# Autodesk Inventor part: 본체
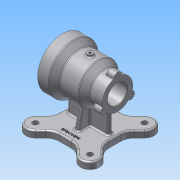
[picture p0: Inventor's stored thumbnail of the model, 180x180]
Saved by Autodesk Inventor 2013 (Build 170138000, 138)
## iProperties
Created: 2017-03
Part Number: 본체
Material: 알루미늄 6061
Document SubType Name: Modeling
Designer: Administrator
Density: 2.71 g/cm^3
Mass: 1008.17 g
Surface Area: 842.601 cm^2
Volume: 372.018 cm^3
Author: Administrator
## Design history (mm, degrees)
sketch "스케치1"
  geometry: L1 (50, 0)-(-50, 0); L2 (-50, 0)-(-50, 45); L3 (50, 27.5)-(27, 27.5); L4 (-30, 45)-(-19, 36); L5 (15, 36)-(27, 27.5); L6 (50, 27.5)-(50, 0); L7 (15, 36)-(-19, 36); L8 (-50, 45)-(-30, 45); L9 (-50, 0)-(-27, 0); L10 (-27, 0)-(-27, 35); L11 (-27, 35)-(-50, 35); L12 (-50, 35)-(-50, 0); L13 (-27, 0)-(20, 0); L14 (20, 0)-(20, 26); L15 (20, 26)-(-27, 26); L16 (-27, 26)-(-27, 0); L17 (20, 0)-(50, 0); L18 (50, 0)-(50, 17.5); L19 (50, 17.5)-(20, 17.5); L20 (20, 17.5)-(20, 0); 2 further points
  constraints: 40 end point, 10 parallel, 4 horizontal, 4 perpendicular, 1 coincident, 1 midpoint, 1 point on line
  dimensions: "d0" = 100 distance of L1.start L1.end; "d8" = 55 diameter of L3 L1; "d9" = 72 diameter of L7 L1; "d10" = 90 diameter of L8 L1; "d12" = 70 diameter of L11 L1; "d13" = 52 diameter of L15 L1; "d14" = 35 diameter of L19 L17; "d15" = 23 distance between parallel lines of L16 L2; "d16" = 47 distance between parallel lines of L14 L10; "d119" = 20 distance of L2.end L4.start; "d120" = 31 horizontal distance of L4.end L2.end; "d121" = 65 horizontal distance of L5.start L2.end; "d122" = 23 distance from line of L6 L3.end
revolve "회전2" sketch "스케치1" stored, may be unused: angle "d17" = 90 deg
chamfer "모따기1" distance "d18" = 1; stored, may be unused: second distance "d19" = 2, angle "d20" = 45 deg
fillet "모깎기1" dims "d21" = 3
node "작업 평면1"
sketch "스케치3"
  geometry: L1 (20.958, -45)-(-20.958, -45); L2 (-45, -20.958)-(-45, 20.958); L3 (-20.958, 45)-(20.958, 45); L4 (0, 0)-(82.902, 0); L5 (49.497, -49.497)-(66.497, -49.497); L6 (49.497, -49.497)-(66.497, -49.497); L7 (61.518, -37.477)-(45, -20.958); L8 (37.477, -61.518)-(20.958, -45); L9 (45, 20.958)-(45, -20.958); L10 (37.477, 61.518)-(20.958, 45); L11 (61.518, 37.477)-(45, 20.958); L12 (-61.518, 37.477)-(-45, 20.958); L13 (-37.477, 61.518)-(-20.958, 45); L14 (-37.477, -61.518)-(-20.958, -45); L15 (-61.518, -37.477)-(-45, -20.958); A1 r 17 centre (49.497, -49.497) between (37.477, -61.518) and (61.518, -37.477); A2 r 17 centre (49.497, 49.497) between (61.518, 37.477) and (37.477, 61.518); A3 r 17 centre (-49.497, 49.497) between (-37.477, 61.518) and (-61.518, 37.477); A4 r 17 centre (-49.497, -49.497) between (-61.518, -37.477) and (-37.477, -61.518); 2 further points
  constraints: 30 end point, 8 point on circle, 4 centre point, 4 horizontal, 3 parallel, 2 tangent, 1 coincident, 1 perpendicular, 33 other
  dimensions: "d25" = 45 distance from line of point (0, 0) L1; "d29" = 34 diameter of A1; "d34" = 360 deg dimension on point (0, 0) L5.start (derived)
extrude "돌출1" join sketch "스케치3" distance "d36" = 12; taper "d37" = 0 deg
fillet "모깎기2" dims "d38" = 25
hole "구멍1" diameter "d41" = 10; stored, may be unused: countersink angle "d45" = 90 deg, drill point angle "d47" = 118 deg; dims "d39" = 10, "d40" = 10, "d42" = 6, "d43" = 4, "d44" = 2, "d46" = 8
sketch "스케치4"
  geometry: L1 (-37, 4)-(37, 4); L2 (37, 4)-(37, -4); L3 (37, -4)-(-37, -4); L4 (-37, -4)-(-37, 4); L5 (-4, 25)-(4, 25); L6 (4, 25)-(4, -25); L7 (4, -25)-(-4, -25); L8 (-4, -25)-(-4, 25); 1 further point
  constraints: 16 end point, 4 parallel, 2 horizontal, 2 perpendicular
  dimensions: "d51" = 4 distance from line of point (0, 0) L1; "d52" = 8 distance of L3.end L1.start; "d53" = 4 distance from line of point (0, 0) L6; "d54" = 8 distance between parallel lines of L6 L8; "d55" = 74 distance of L1.start L1.end; "d56" = 37 distance from line of point (0, 0) L2; "d58" = 25 distance from line of L5 point (0, 0); "d124" = 25 distance from line of L7 point (0, 0)
extrude "돌출2" join sketch "스케치4" stored distance "d59" = 12; taper "d60" = 0 deg
extrude "돌출3" join sketch "스케치4" stored distance "d61" = 12; taper "d62" = 0 deg
feature "면 기울기1" dims angle "d63" = 10 deg
feature "면 기울기2" dims angle "d64" = 10 deg
fillet "모깎기3" dims "d65" = 3
node "작업 평면2"
sketch "스케치5"
  geometry: C1 r 5 at (0, 0); 1 further point
  constraints: 1 centre point, 1 coincident
  dimensions: "d67" = 10 diameter of C1
extrude "돌출4" join sketch "스케치5" stored distance "d68" = 12; taper "d69" = 0 deg
fillet "모깎기4" dims "d70" = 3
hole "구멍2" diameter "d73" = 4.1; stored, may be unused: countersink angle "d77" = 90 deg, drill point angle "d79" = 118 deg; dims "d71" = 10, "d72" = 10, "d74" = 6, "d75" = 4, "d76" = 2, "d78" = 30
sketch "스케치6"
  geometry: A1 r 27.5 centre (0, 0) between (0, 27.5) and (-6.943, 26.609) reference; A2 r 7 centre (0, 27.5) between (6.943, 26.609) and (-6.943, 26.609)
  constraints: 5 point on circle, 1 centre point
  dimensions: "d80" = 14 diameter of A2
extrude "돌출5" join sketch "스케치6" distance "d81" = 15; taper "d82" = 0 deg
fillet "모깎기5" dims "d83" = 3
fillet "모깎기6" dims "d84" = 1
hole "구멍3" diameter "d87" = 3.2; stored, may be unused: countersink angle "d91" = 90 deg, drill point angle "d93" = 118 deg; dims "d88" = 9, "d89" = 4, "d90" = 2, "d92" = 11, "d94" = 10, "d95" = 10
fillet "모깎기7" dims "d99" = 3
sketch "스케치7"
  geometry: 1 further point
hole "구멍4" sketch "스케치7" at (0, 40) diameter "d101" = 3.2; stored, may be unused: countersink angle "d105" = 90 deg, drill point angle "d107" = 118 deg; dims "d102" = 9, "d103" = 4, "d104" = 2, "d106" = 11
node "작업 평면3"
sketch "스케치9"
  geometry: L1 (45, -10.603)-(45, 10.603) reference; 3 further points
  constraints: 1 coincident, 1 other
  dimensions: "d114" = 35 distance of point (0, 0) point (0, -35); "d115" = 45 distance from line of L1 point (0, -35)
feature "엠보싱1" sketch "스케치9" dims "d0" = 100, "d8" = 55, "d9" = 72, "d10" = 90, "d12" = 70, "d13" = 52, "d14" = 35, "d15" = 23, "d16" = 47, "d116" = 0.5, "d117" = 0, "d119" = 20, "d120" = 31, "d121" = 65, "d122" = 23
fillet "모깎기8" dims "d118" = 3
node "솔리드2"
pattern_circular "원형 패턴1" dims angle "d49" = 360 deg
pattern_circular "원형 패턴2" dims "d97" = 360 deg
pattern_circular "원형 패턴3" dims angle "d109" = 360 deg
other parameters: "d2" = 72, "d6" = 65, "d7" = 23, "d22" = -82, "d111" = 21.5
